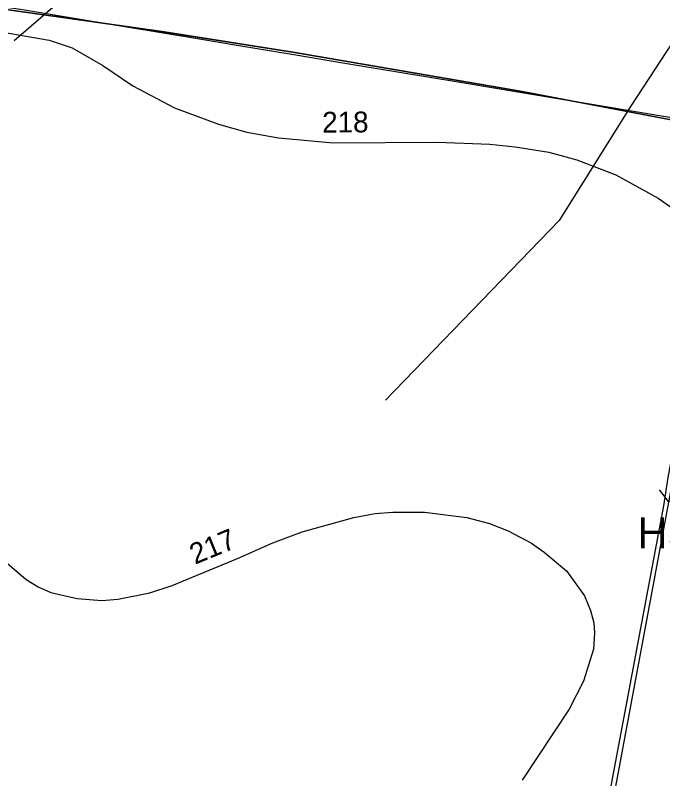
# Model space of a CAD drawing. Extents: x -662500 to -655523, y -1056000 to -1049993.
# Drawn here: x -660725.5 to -660413.7, y -1053965.2 to -1053597.4 of the extents above; entities that cross this region are included whole.
import ezdxf

# ---------------------------------------------------------------- set-up
doc = ezdxf.new("R2010")
doc.units = 0
for name, color, linetype in [('58', 7, 'Continuous'), ('Vrstva 1', 7, 'Continuous'), ('Vrstva 17', 7, 'Continuous'), ('Vrstva 24', 7, 'Continuous'), ('Vrstva 5', 7, 'Continuous'), ('Vrstva 57', 7, 'Continuous'), ('Vrstva 7', 7, 'Continuous')]:
    doc.layers.add(name, color=color, linetype=linetype)

# ---------------------------------------------------------------- blocks, each defined once
blk = doc.blocks.new('PSZ019')
at = {"layer": 'Vrstva 17'}
blk.add_lwpolyline([(-10, -5), (-5, 0), (5, 0), (10, -5)], dxfattribs=at)

msp = doc.modelspace()

# ---------------------------------------------------------------- linework, layer by layer
at = {"layer": '58'}
msp.add_lwpolyline([(-660445.86, -1054007.95), (-660413.19, -1053833.64), (-660411, -1053820.07), (-660384.31, -1053676.75), (-660379.64, -1053651.71), (-660490.15, -1053633.33), (-660513.22, -1053629.49), (-660539.56, -1053625.11), (-660565.82, -1053620.75), (-660592.33, -1053616.34), (-660618.84, -1053611.93), (-660635.87, -1053609.1), (-660659.17, -1053605.23), (-660692.27, -1053599.72), (-660722.92, -1053594.62), (-660747.91, -1053591.01)], dxfattribs=at)
at = {"layer": 'Vrstva 1'}
msp.add_lwpolyline([(-660438.94, -1053983.58), (-660410.34, -1053829.44), (-660408.79, -1053821.07), (-660408.56, -1053819.81), (-660407.77, -1053814.99), (-660398.86, -1053759.98), (-660378.28, -1053653.76), (-660412.36, -1053647.26), (-660481.41, -1053634.1), (-660522.43, -1053627.05), (-660591.82, -1053615.12), (-660653.75, -1053605.31), (-660728.84, -1053594.86), (-660735.74, -1053593.9), (-660749.01, -1053592.05)], dxfattribs=at)
at = {"layer": 'Vrstva 24'}
msp.add_lwpolyline([(-660726, -1053609.5), (-660705.14, -1053591.51), (-660671.5, -1053562.5), (-660660, -1053547.5)], dxfattribs=at)
at = {"layer": 'Vrstva 5'}
msp.add_lwpolyline([(-660728.84, -1053594.86), (-660659.38, -1053604.53), (-660591.82, -1053615.12), (-660481.41, -1053634.1), (-660378.28, -1053653.76), (-660398.86, -1053759.98), (-660407.77, -1053814.99), (-660406.28, -1053815.33), (-660305.92, -1053826.68), (-660234.87, -1053832.54), (-660162.97, -1053835.81), (-660159.44, -1053804.48), (-660157.5, -1053793.95), (-660158.49, -1053793), (-660150.34, -1053712.33), (-660136.95, -1053566.03)], dxfattribs=at)
msp.add_lwpolyline([(-660410.34, -1053829.44), (-660358.01, -1053836.31), (-660307.68, -1053842.9), (-660239.81, -1053850.04), (-660157.09, -1053852.56), (-660122.2, -1053852.55), (-660088.98, -1053852.83), (-660073.51, -1053852.41), (-660070.7, -1053876.72), (-660055.8, -1053876.8), (-660042.1, -1053979.18), (-660077.54, -1053979.35), (-660076.72, -1054000.14), (-660201.14, -1054026.33), (-660241.12, -1054042.52), (-660324.21, -1054084.16), (-660365.41, -1054097.44), (-660421.6, -1054104.02), (-660440.68, -1054035.17), (-660444.92, -1054007.24), (-660438.94, -1053983.58)], close=True, dxfattribs=at)
at = {"layer": 'Vrstva 57'}
msp.add_lwpolyline([(-660161.77, -1053238.23), (-660180.21, -1053289.29), (-660196.67, -1053318.48), (-660229.8, -1053370.88), (-660276.09, -1053424.22), (-660304.29, -1053466.28), (-660392.17, -1053584.48), (-660428.83, -1053640.88), (-660463.61, -1053696.33), (-660547.26, -1053782.81)], dxfattribs=at)
at = {"layer": 'Vrstva 7'}
for p, q in [((-660734.53, -1053605.06), (-660717.45, -1053607.87)), ((-660717.45, -1053607.87), (-660709.23, -1053609.43)), ((-660709.23, -1053609.43), (-660698.18, -1053613.11)), ((-660698.18, -1053613.11), (-660683.3, -1053621.61)), ((-660683.3, -1053621.61), (-660668.85, -1053631.39)), ((-660668.85, -1053631.39), (-660648.86, -1053642.02)), ((-660648.86, -1053642.02), (-660627.61, -1053649.82)), ((-660627.61, -1053649.82), (-660614, -1053653.64)), ((-660614, -1053653.64), (-660598.7, -1053656.48)), ((-660598.7, -1053656.48), (-660572.34, -1053658.89)), ((-660572.34, -1053658.89), (-660522.17, -1053658.6)), ((-660522.17, -1053658.6), (-660496.94, -1053659.45)), ((-660496.94, -1053659.45), (-660484.76, -1053660.73)), ((-660484.76, -1053660.73), (-660468.6, -1053663.42)), ((-660468.6, -1053663.42), (-660455, -1053666.96)), ((-660455, -1053666.96), (-660436.29, -1053674.19)), ((-660436.29, -1053674.19), (-660415.88, -1053685.53)), ((-660415.88, -1053685.53), (-660405.68, -1053692.76)), ((-660562.42, -1053839.29), (-660552.21, -1053837.45)), ((-660552.21, -1053837.45), (-660543.71, -1053836.74)), ((-660543.71, -1053836.74), (-660528.41, -1053836.74)), ((-660528.41, -1053836.74), (-660508, -1053839.29)), ((-660587.36, -1053846.24), (-660562.42, -1053839.29)), ((-660508, -1053839.29), (-660497.09, -1053842.27)), ((-660497.09, -1053842.27), (-660488.16, -1053845.81)), ((-660601.53, -1053851.48), (-660587.36, -1053846.24)), ((-660488.16, -1053845.81), (-660476.96, -1053851.76)), ((-660618.54, -1053859.13), (-660601.53, -1053851.48)), ((-660476.96, -1053851.76), (-660470.87, -1053856.01)), ((-660736.45, -1053855.45), (-660720.29, -1053869.19)), ((-660470.87, -1053856.01), (-660460.1, -1053864.94)), ((-660650, -1053872.03), (-660618.54, -1053859.13)), ((-660460.1, -1053864.94), (-660451.45, -1053876.99)), ((-660720.29, -1053869.19), (-660714.48, -1053872.74)), ((-660714.48, -1053872.74), (-660708.39, -1053875.43)), ((-660660.77, -1053875.57), (-660650, -1053872.03)), ((-660708.39, -1053875.43), (-660695.63, -1053878.26)), ((-660695.63, -1053878.26), (-660683.87, -1053879.26)), ((-660683.87, -1053879.26), (-660676.07, -1053878.69)), ((-660676.07, -1053878.69), (-660660.77, -1053875.57)), ((-660451.45, -1053876.99), (-660448.48, -1053884.07)), ((-660448.48, -1053884.07), (-660446.92, -1053890.03)), ((-660446.92, -1053890.03), (-660446.49, -1053894.84)), ((-660446.49, -1053894.84), (-660447.06, -1053902.78)), ((-660447.06, -1053902.78), (-660451.88, -1053918.23)), ((-660451.88, -1053918.23), (-660458.82, -1053931.69)), ((-660458.82, -1053931.69), (-660481.35, -1053965.84))]:
    msp.add_line(p, q, dxfattribs=at)

# ---------------------------------------------------------------- block references
at = {"layer": 'Vrstva 17', "rotation": 172.35543899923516}
msp.add_blockref('PSZ019', (-660406, -1053832.26), dxfattribs=at)

# ---------------------------------------------------------------- texts
at = {"layer": 'Vrstva 17'}
msp.add_text('HS6', height=15, rotation=360, dxfattribs=at).set_placement((-660425.86, -1053854.24))
at = {"layer": 'Vrstva 7'}
for s, rotation, p in [('218', 0.3232, (-660577.67, -1053653.91)), ('217', 22.2889, (-660638.97, -1053862.1))]:
    msp.add_text(s, height=10, rotation=rotation, dxfattribs=at).set_placement(p)

doc.saveas('drawing.dxf')
